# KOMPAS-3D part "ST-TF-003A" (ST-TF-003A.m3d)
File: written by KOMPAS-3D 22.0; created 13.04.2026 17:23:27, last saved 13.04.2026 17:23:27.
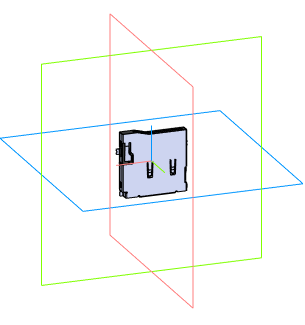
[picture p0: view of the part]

Document properties: Автор: Andrey; Полное имя файла: C:\Users\User1\Documents\ST-TF-003A.m3d

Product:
- Part/product: ST-TF-003A

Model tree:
1. Операция без истории:1
2. Операция без истории:2
3. Операция без истории:3
4. Операция без истории:4
5. Операция без истории:5
6. Операция без истории:6
7. Операция без истории:7
8. Операция без истории:8
9. Операция без истории:9
10. Операция без истории:10
11. Операция без истории:11
12. Операция без истории:12
13. Операция без истории:13
14. Операция без истории:14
